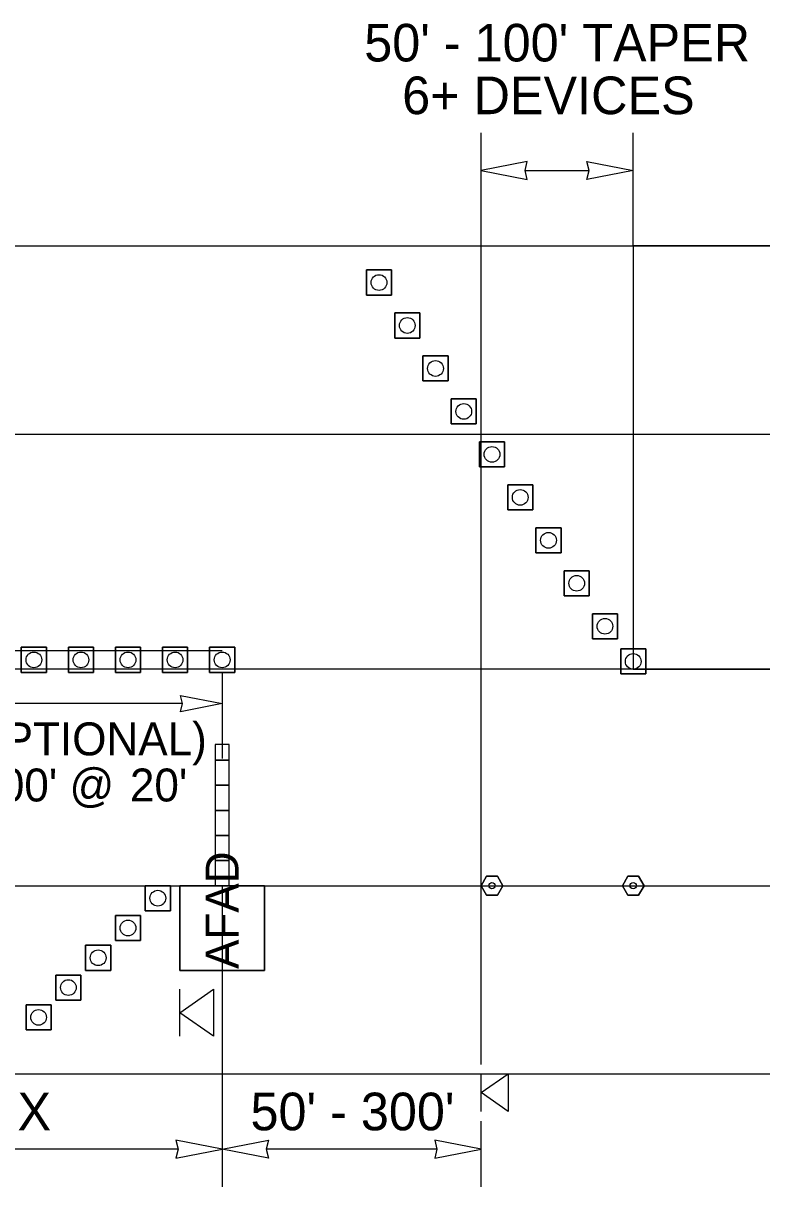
# Model space of a CAD drawing. Extents: x 99999.1 to 100095.7, y 99995 to 100010.7.
# Drawn here: x 100043.854 to 100045.423, y 100005.492 to 100007.966 of the extents above; entities that cross this region are included whole.
import ezdxf

# ---------------------------------------------------------------- set-up
doc = ezdxf.new("R2010")
doc.units = 0
for name, color, linetype in [('RD_ED_ShoulderPavedEdge', 7, 'Continuous'), ('RD_MK_LineEdgeWhite', 7, 'Continuous'), ('RD_MK_LineNoPass', 7, 'Continuous'), ('RD_MK_LineSkipCenter', 7, 'Continuous'), ('TR_WZ_AFAD', 7, 'Continuous'), ('TR_WZ_PortableSignMountBlk-Wht', 7, 'Continuous'), ('TR_WZ_TrafficCone', 7, 'Continuous'), ('TR_WZ_TubularMarker', 7, 'Continuous'), ('TR_WZ_WorkZoneDetails', 7, 'Continuous'), ('TR_WZ_WorkZoneTextCurrent', 7, 'Continuous')]:
    doc.layers.add(name, color=color, linetype=linetype)

msp = doc.modelspace()

# ---------------------------------------------------------------- linework, layer by layer
at = {"layer": 'RD_ED_ShoulderPavedEdge'}
for p, q in [((100040.1076, 100007.4923), (100055.6424, 100007.4923)), ((100040.1076, 100005.7323), (100055.6424, 100005.7323))]:
    msp.add_line(p, q, dxfattribs=at)
at = {"layer": 'RD_MK_LineEdgeWhite'}
for p, q in [((100040.1076, 100007.0923), (100055.6424, 100007.0923)), ((100040.1076, 100006.1323), (100055.6424, 100006.1323))]:
    msp.add_line(p, q, dxfattribs=at)
at = {"layer": 'RD_MK_LineNoPass'}
msp.add_line((100043.4767, 100006.6323), (100044.2767, 100006.6323), dxfattribs=at)
at = {"layer": 'RD_MK_LineSkipCenter'}
msp.add_lwpolyline([(100051.15, 100006.5923), (100043.4767, 100006.5923)], dxfattribs=at)
at = {"layer": 'TR_WZ_AFAD'}
for p, q in [((100044.2916, 100006.399), (100044.2916, 100006.4323)), ((100044.2616, 100006.399), (100044.2616, 100006.3457)), ((100044.2616, 100006.399), (100044.2766, 100006.399)), ((100044.2766, 100006.399), (100044.2916, 100006.399)), ((100044.2916, 100006.3457), (100044.2916, 100006.399)), ((100044.2616, 100006.3457), (100044.2616, 100006.2923)), ((100044.2766, 100006.3457), (100044.2616, 100006.3457)), ((100044.2916, 100006.3457), (100044.2766, 100006.3457)), ((100044.2916, 100006.2923), (100044.2916, 100006.3457)), ((100044.2616, 100006.2923), (100044.2616, 100006.239)), ((100044.2616, 100006.2923), (100044.2766, 100006.2923)), ((100044.2766, 100006.2923), (100044.2916, 100006.2923)), ((100044.2916, 100006.239), (100044.2916, 100006.2923)), ((100044.2766, 100006.239), (100044.2616, 100006.239)), ((100044.2616, 100006.239), (100044.2616, 100006.1857)), ((100044.2916, 100006.239), (100044.2766, 100006.239)), ((100044.2916, 100006.1857), (100044.2916, 100006.239)), ((100044.2616, 100006.1857), (100044.2616, 100006.1323)), ((100044.1866, 100005.9523), (100044.1866, 100006.1323)), ((100044.1866, 100006.1323), (100044.3666, 100006.1323)), ((100044.27, 100006.1323), (100044.1866, 100006.1323)), ((100044.1866, 100006.1323), (100044.1866, 100005.9523)), ((100044.2616, 100006.1323), (100044.27, 100006.1323)), ((100044.27, 100006.1323), (100044.2766, 100006.1323)), ((100044.3666, 100006.1323), (100044.3666, 100005.9523)), ((100044.3666, 100005.9523), (100044.3666, 100006.1323)), ((100044.3666, 100005.9523), (100044.1866, 100005.9523)), ((100044.1866, 100005.9523), (100044.3666, 100005.9523))]:
    msp.add_line(p, q, dxfattribs=at)
for points in [[(100044.2916, 100006.4323), (100044.2616, 100006.4323), (100044.2616, 100006.399)], [(100044.2916, 100006.1323), (100044.2916, 100006.4323), (100044.2616, 100006.4323), (100044.2616, 100006.1323)], [(100044.2916, 100006.399), (100044.2766, 100006.399), (100044.2616, 100006.399)], [(100044.2616, 100006.3457), (100044.2766, 100006.3457), (100044.2916, 100006.3457)], [(100044.2916, 100006.2923), (100044.2766, 100006.2923), (100044.2616, 100006.2923)], [(100044.2616, 100006.239), (100044.2766, 100006.239), (100044.2916, 100006.239)], [(100044.2916, 100006.1857), (100044.2766, 100006.1857), (100044.2616, 100006.1857)], [(100044.2616, 100006.1857), (100044.2766, 100006.1857), (100044.2916, 100006.1857)], [(100044.2766, 100006.1323), (100044.2833, 100006.1323), (100044.2916, 100006.1323), (100044.2916, 100006.1857)], [(100044.3666, 100006.1323), (100044.2833, 100006.1323), (100044.27, 100006.1323)]]:
    msp.add_lwpolyline(points, dxfattribs=at)
at = {"layer": 'TR_WZ_PortableSignMountBlk-Wht'}
for p, q in [((100044.1867, 100005.8123), (100044.1867, 100005.9123)), ((100044.8267, 100005.6523), (100044.8267, 100005.7323))]:
    msp.add_line(p, q, dxfattribs=at)
for points in [[(100044.1867, 100005.8622), (100044.2585, 100005.9123), (100044.2585, 100005.8123)], [(100044.8267, 100005.6923), (100044.8841, 100005.7323), (100044.8841, 100005.6523)]]:
    msp.add_lwpolyline(points, close=True, dxfattribs=at)
at = {"layer": 'TR_WZ_TrafficCone'}
for points in [[(100044.6367, 100007.4411), (100044.5834, 100007.4411), (100044.5834, 100007.3877), (100044.6367, 100007.3877), (100044.6367, 100007.4411)], [(100044.6367, 100007.3877), (100044.5834, 100007.3877), (100044.5834, 100007.4411), (100044.6367, 100007.4411), (100044.6367, 100007.3877)], [(100044.6967, 100007.3497), (100044.6434, 100007.3497), (100044.6434, 100007.2964), (100044.6967, 100007.2964), (100044.6967, 100007.3497)], [(100044.6967, 100007.2964), (100044.6434, 100007.2964), (100044.6434, 100007.3497), (100044.6967, 100007.3497), (100044.6967, 100007.2964)], [(100044.7567, 100007.2584), (100044.7034, 100007.2584), (100044.7034, 100007.2051), (100044.7567, 100007.2051), (100044.7567, 100007.2584)], [(100044.7567, 100007.2051), (100044.7034, 100007.2051), (100044.7034, 100007.2584), (100044.7567, 100007.2584), (100044.7567, 100007.2051)], [(100044.8167, 100007.1671), (100044.7634, 100007.1671), (100044.7634, 100007.1137), (100044.8167, 100007.1137), (100044.8167, 100007.1671)], [(100044.8167, 100007.1137), (100044.7634, 100007.1137), (100044.7634, 100007.1671), (100044.8167, 100007.1671), (100044.8167, 100007.1137)], [(100044.8234, 100007.0757), (100044.8767, 100007.0757), (100044.8767, 100007.0224), (100044.8234, 100007.0224), (100044.8234, 100007.0757)], [(100044.8234, 100007.0224), (100044.8767, 100007.0224), (100044.8767, 100007.0757), (100044.8234, 100007.0757), (100044.8234, 100007.0224)], [(100044.8834, 100006.9844), (100044.9367, 100006.9844), (100044.9367, 100006.9311), (100044.8834, 100006.9311), (100044.8834, 100006.9844)], [(100044.8834, 100006.9311), (100044.9367, 100006.9311), (100044.9367, 100006.9844), (100044.8834, 100006.9844), (100044.8834, 100006.9311)], [(100044.9434, 100006.8931), (100044.9967, 100006.8931), (100044.9967, 100006.8397), (100044.9434, 100006.8397), (100044.9434, 100006.8931)], [(100044.9434, 100006.8397), (100044.9967, 100006.8397), (100044.9967, 100006.8931), (100044.9434, 100006.8931), (100044.9434, 100006.8397)], [(100045.0034, 100006.8017), (100045.0567, 100006.8017), (100045.0567, 100006.7484), (100045.0034, 100006.7484), (100045.0034, 100006.8017)], [(100045.0034, 100006.7484), (100045.0567, 100006.7484), (100045.0567, 100006.8017), (100045.0034, 100006.8017), (100045.0034, 100006.7484)], [(100045.0634, 100006.7104), (100045.1167, 100006.7104), (100045.1167, 100006.6571), (100045.0634, 100006.6571), (100045.0634, 100006.7104)], [(100045.0634, 100006.6571), (100045.1167, 100006.6571), (100045.1167, 100006.7104), (100045.0634, 100006.7104), (100045.0634, 100006.6571)], [(100043.9033, 100006.639), (100043.85, 100006.639), (100043.85, 100006.5857), (100043.9033, 100006.5857), (100043.9033, 100006.639)], [(100043.9033, 100006.5857), (100043.85, 100006.5857), (100043.85, 100006.639), (100043.9033, 100006.639), (100043.9033, 100006.5857)], [(100044.0033, 100006.639), (100043.95, 100006.639), (100043.95, 100006.5857), (100044.0033, 100006.5857), (100044.0033, 100006.639)], [(100044.0033, 100006.5857), (100043.95, 100006.5857), (100043.95, 100006.639), (100044.0033, 100006.639), (100044.0033, 100006.5857)], [(100044.1033, 100006.639), (100044.05, 100006.639), (100044.05, 100006.5857), (100044.1033, 100006.5857), (100044.1033, 100006.639)], [(100044.1033, 100006.5857), (100044.05, 100006.5857), (100044.05, 100006.639), (100044.1033, 100006.639), (100044.1033, 100006.5857)], [(100044.2033, 100006.639), (100044.15, 100006.639), (100044.15, 100006.5857), (100044.2033, 100006.5857), (100044.2033, 100006.639)], [(100044.2033, 100006.5857), (100044.15, 100006.5857), (100044.15, 100006.639), (100044.2033, 100006.639), (100044.2033, 100006.5857)], [(100044.3033, 100006.639), (100044.25, 100006.639), (100044.25, 100006.5857), (100044.3033, 100006.5857), (100044.3033, 100006.639)], [(100044.3033, 100006.5857), (100044.25, 100006.5857), (100044.25, 100006.639), (100044.3033, 100006.639), (100044.3033, 100006.5857)], [(100045.1234, 100006.6357), (100045.1767, 100006.6357), (100045.1767, 100006.5823), (100045.1234, 100006.5823), (100045.1234, 100006.6357)], [(100045.1234, 100006.5823), (100045.1767, 100006.5823), (100045.1767, 100006.6357), (100045.1234, 100006.6357), (100045.1234, 100006.5823)], [(100044.1133, 100006.1323), (100044.1667, 100006.1323), (100044.1667, 100006.079), (100044.1133, 100006.079), (100044.1133, 100006.1323)], [(100044.1133, 100006.079), (100044.1667, 100006.079), (100044.1667, 100006.1323), (100044.1133, 100006.1323), (100044.1133, 100006.079)], [(100044.05, 100006.069), (100044.1033, 100006.069), (100044.1033, 100006.0157), (100044.05, 100006.0157), (100044.05, 100006.069)], [(100044.05, 100006.0157), (100044.1033, 100006.0157), (100044.1033, 100006.069), (100044.05, 100006.069), (100044.05, 100006.0157)], [(100043.9867, 100006.0057), (100044.04, 100006.0057), (100044.04, 100005.9523), (100043.9867, 100005.9523), (100043.9867, 100006.0057)], [(100043.9867, 100005.9523), (100044.04, 100005.9523), (100044.04, 100006.0057), (100043.9867, 100006.0057), (100043.9867, 100005.9523)], [(100043.9767, 100005.9423), (100043.9233, 100005.9423), (100043.9233, 100005.889), (100043.9767, 100005.889), (100043.9767, 100005.9423)], [(100043.9767, 100005.889), (100043.9233, 100005.889), (100043.9233, 100005.9423), (100043.9767, 100005.9423), (100043.9767, 100005.889)], [(100043.9133, 100005.879), (100043.86, 100005.879), (100043.86, 100005.8257), (100043.9133, 100005.8257), (100043.9133, 100005.879)], [(100043.9133, 100005.8257), (100043.86, 100005.8257), (100043.86, 100005.879), (100043.9133, 100005.879), (100043.9133, 100005.8257)]]:
    msp.add_lwpolyline(points, dxfattribs=at)
for centre in [(100044.61, 100007.4144), (100044.67, 100007.3231), (100044.73, 100007.2317), (100044.79, 100007.1404), (100044.85, 100007.0491), (100044.91, 100006.9577), (100044.97, 100006.8664), (100045.03, 100006.7751), (100045.09, 100006.6837), (100043.8767, 100006.6123), (100043.9767, 100006.6123), (100044.0767, 100006.6123), (100044.1767, 100006.6123), (100044.2767, 100006.6123), (100045.15, 100006.609), (100044.14, 100006.1057), (100044.0767, 100006.0423), (100044.0133, 100005.979), (100043.95, 100005.9157), (100043.8867, 100005.8523)]:
    msp.add_circle(centre, 0.0167, dxfattribs=at)
at = {"layer": 'TR_WZ_TubularMarker'}
for points in [[(100044.8269, 100006.1323), (100044.8385, 100006.1523), (100044.8616, 100006.1523), (100044.8731, 100006.1323), (100044.8616, 100006.1123), (100044.8385, 100006.1123)], [(100045.1269, 100006.1323), (100045.1385, 100006.1523), (100045.1616, 100006.1523), (100045.1731, 100006.1323), (100045.1616, 100006.1123), (100045.1385, 100006.1123)]]:
    msp.add_lwpolyline(points, close=True, dxfattribs=at)
for points in [[(100044.8385, 100006.1123), (100044.8616, 100006.1123), (100044.8731, 100006.1323), (100044.8616, 100006.1523), (100044.8385, 100006.1523), (100044.8269, 100006.1323), (100044.8385, 100006.1123)], [(100045.1385, 100006.1123), (100045.1616, 100006.1123), (100045.1731, 100006.1323), (100045.1616, 100006.1523), (100045.1385, 100006.1523), (100045.1269, 100006.1323), (100045.1385, 100006.1123)]]:
    msp.add_lwpolyline(points, dxfattribs=at)
for centre in [(100044.85, 100006.1323), (100045.15, 100006.1323)]:
    msp.add_circle(centre, 0.00667, dxfattribs=at)
at = {"layer": 'TR_WZ_WorkZoneDetails'}
for p, q in [((100044.8267, 100005.7523), (100044.8267, 100007.7323)), ((100045.15, 100007.4923), (100045.15, 100007.7323)), ((100044.9204, 100007.6523), (100045.0563, 100007.6523)), ((100044.2767, 100006.5857), (100044.2767, 100006.4023)), ((100044.1923, 100006.5193), (100043.761, 100006.5193)), ((100044.2767, 100006.1323), (100044.2767, 100005.4923)), ((100044.8267, 100005.4923), (100044.8267, 100005.6319)), ((100044.1829, 100005.5723), (100043.5704, 100005.5723)), ((100044.7329, 100005.5723), (100044.3704, 100005.5723))]:
    msp.add_line(p, q, dxfattribs=at)
for points in [[(100044.8267, 100007.6523), (100044.9249, 100007.6331), (100044.9204, 100007.6523), (100044.9249, 100007.6716)], [(100045.15, 100007.6523), (100045.0517, 100007.6331), (100045.0563, 100007.6523), (100045.0517, 100007.6716)], [(100045.15, 100007.4923), (100045.15, 100006.5923), (100049.9338, 100006.5923), (100049.9338, 100007.4923)], [(100044.2767, 100006.5193), (100044.1882, 100006.502), (100044.1923, 100006.5193), (100044.1882, 100006.5367)], [(100044.2767, 100005.5723), (100044.1784, 100005.5916), (100044.1829, 100005.5723), (100044.1784, 100005.5531)], [(100044.2767, 100005.5723), (100044.3749, 100005.5916), (100044.3704, 100005.5723), (100044.3749, 100005.5531)], [(100044.8267, 100005.5723), (100044.7284, 100005.5916), (100044.7329, 100005.5723), (100044.7284, 100005.5531)]]:
    msp.add_lwpolyline(points, close=True, dxfattribs=at)

# ---------------------------------------------------------------- texts
at = {"layer": 'TR_WZ_AFAD'}
msp.add_text('AFAD', height=0.07, rotation=90, dxfattribs=at).set_placement((100044.3116, 100005.9553))
at = {"layer": 'TR_WZ_WorkZoneTextCurrent'}
for s, p in [("50' - 100' TAPER", (100044.5786, 100007.8843)), ('6+ DEVICES', (100044.6592, 100007.7723)), ('X', (100043.8419, 100005.6123)), ("50' - 300'", (100044.3369, 100005.6123))]:
    msp.add_text(s, height=0.08, rotation=360, dxfattribs=at).set_placement(p)
for s, p in [('(OPTIONAL)', (100043.7085, 100006.4093)), ("300' @", (100043.7523, 100006.3113)), ("20'", (100044.0807, 100006.3113))]:
    msp.add_text(s, height=0.07, dxfattribs=at).set_placement(p)

doc.saveas('drawing.dxf')
